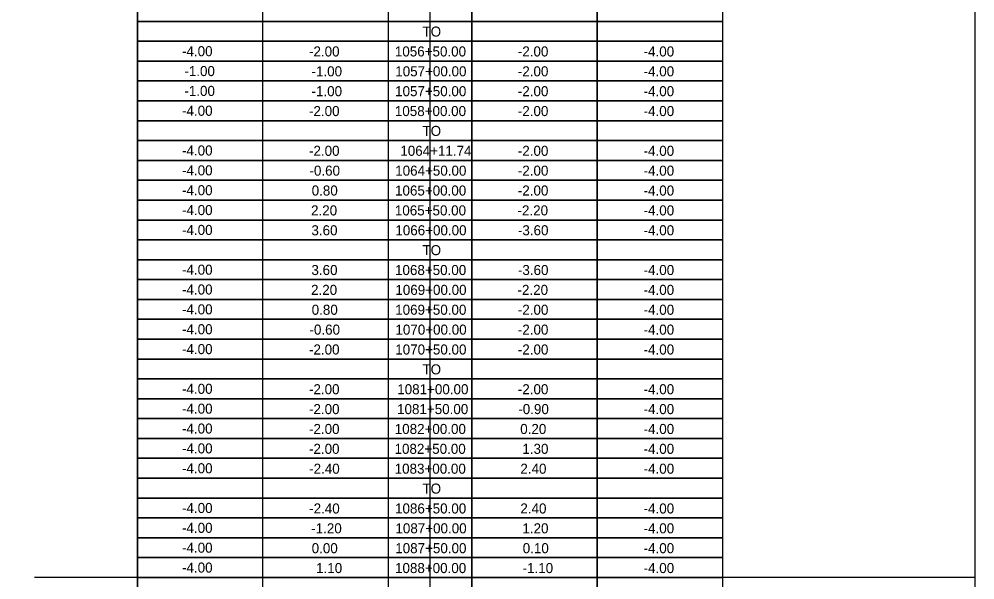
# Model space of a CAD drawing. Extents: x 1026502 to 1027102, y 781811 to 782040.
# Drawn here: x 1026944.94 to 1026990.71, y 781869.21 to 781896.04 of the extents above; entities that cross this region are included whole.
import ezdxf

# ---------------------------------------------------------------- set-up
doc = ezdxf.new("R2010")
doc.units = 0
for name, color, linetype in [('ANNOTATION', 7, 'Continuous'), ('BORDER', 7, 'Continuous'), ('DIMENSIONS', 7, 'Continuous')]:
    doc.layers.add(name, color=color, linetype=linetype)

msp = doc.modelspace()

# ---------------------------------------------------------------- linework, layer by layer
at = {"layer": 'ANNOTATION'}
for points in [[(1026917.619, 781923.493), (1026950.619, 781923.493), (1026950.619, 781846.737), (1026917.619, 781846.737)], [(1026950.619, 781923.493), (1026978.619, 781923.493), (1026978.619, 781869.32), (1026950.619, 781869.32)]]:
    msp.add_lwpolyline(points, close=True, dxfattribs=at)
at = {"layer": 'BORDER'}
for p, q in [((1026964.619, 781922.543), (1026964.619, 781816.098)), ((1026990.71, 781922.543), (1026990.71, 781816.098)), ((1026953.619, 781895.931), (1026950.619, 781895.931)), ((1026953.619, 781895.931), (1026950.619, 781895.931)), ((1026953.619, 781895.931), (1026956.619, 781895.931)), ((1026953.619, 781894.981), (1026950.619, 781894.981)), ((1026953.619, 781894.981), (1026950.619, 781894.981)), ((1026953.619, 781894.981), (1026956.619, 781894.981)), ((1026953.619, 781894.031), (1026950.619, 781894.031)), ((1026953.619, 781894.031), (1026950.619, 781894.031)), ((1026953.619, 781894.031), (1026956.619, 781894.031)), ((1026953.619, 781893.08), (1026950.619, 781893.08)), ((1026953.619, 781893.08), (1026950.619, 781893.08)), ((1026953.619, 781893.08), (1026956.619, 781893.08)), ((1026953.619, 781892.13), (1026950.619, 781892.13)), ((1026953.619, 781892.13), (1026950.619, 781892.13)), ((1026953.619, 781892.13), (1026956.619, 781892.13)), ((1026953.619, 781891.179), (1026950.619, 781891.179)), ((1026953.619, 781891.179), (1026950.619, 781891.179)), ((1026953.619, 781891.179), (1026956.619, 781891.179)), ((1026953.619, 781890.229), (1026950.619, 781890.229)), ((1026953.619, 781890.229), (1026950.619, 781890.229)), ((1026953.619, 781890.229), (1026956.619, 781890.229)), ((1026953.619, 781889.279), (1026950.619, 781889.279)), ((1026953.619, 781889.279), (1026950.619, 781889.279)), ((1026953.619, 781889.279), (1026956.619, 781889.279)), ((1026953.619, 781888.328), (1026950.619, 781888.328)), ((1026953.619, 781888.328), (1026950.619, 781888.328)), ((1026953.619, 781888.328), (1026956.619, 781888.328)), ((1026953.619, 781887.378), (1026950.619, 781887.378)), ((1026953.619, 781887.378), (1026950.619, 781887.378)), ((1026953.619, 781887.378), (1026956.619, 781887.378)), ((1026953.619, 781886.427), (1026950.619, 781886.427)), ((1026953.619, 781886.427), (1026950.619, 781886.427)), ((1026953.619, 781886.427), (1026956.619, 781886.427)), ((1026953.619, 781885.477), (1026950.619, 781885.477)), ((1026953.619, 781885.477), (1026950.619, 781885.477)), ((1026953.619, 781885.477), (1026956.619, 781885.477)), ((1026953.619, 781884.527), (1026950.619, 781884.527)), ((1026953.619, 781884.527), (1026950.619, 781884.527)), ((1026953.619, 781884.527), (1026956.619, 781884.527)), ((1026953.619, 781883.576), (1026950.619, 781883.576)), ((1026953.619, 781883.576), (1026950.619, 781883.576)), ((1026953.619, 781883.576), (1026956.619, 781883.576)), ((1026953.619, 781882.626), (1026950.619, 781882.626)), ((1026953.619, 781882.626), (1026950.619, 781882.626)), ((1026953.619, 781882.626), (1026956.619, 781882.626)), ((1026953.619, 781881.675), (1026950.619, 781881.675)), ((1026953.619, 781881.675), (1026950.619, 781881.675)), ((1026953.619, 781881.675), (1026956.619, 781881.675)), ((1026953.619, 781880.725), (1026950.619, 781880.725)), ((1026953.619, 781880.725), (1026950.619, 781880.725)), ((1026953.619, 781880.725), (1026956.619, 781880.725)), ((1026953.619, 781879.775), (1026950.619, 781879.775)), ((1026953.619, 781879.775), (1026950.619, 781879.775)), ((1026953.619, 781879.775), (1026956.619, 781879.775)), ((1026953.619, 781878.824), (1026950.619, 781878.824)), ((1026953.619, 781878.824), (1026950.619, 781878.824)), ((1026953.619, 781878.824), (1026956.619, 781878.824)), ((1026953.619, 781877.874), (1026950.619, 781877.874)), ((1026953.619, 781877.874), (1026950.619, 781877.874)), ((1026953.619, 781877.874), (1026956.619, 781877.874)), ((1026953.619, 781876.923), (1026950.619, 781876.923)), ((1026953.619, 781876.923), (1026950.619, 781876.923)), ((1026953.619, 781876.923), (1026956.619, 781876.923)), ((1026953.619, 781875.973), (1026950.619, 781875.973)), ((1026953.619, 781875.973), (1026950.619, 781875.973)), ((1026953.619, 781875.973), (1026956.619, 781875.973)), ((1026953.619, 781875.023), (1026950.619, 781875.023)), ((1026953.619, 781875.023), (1026950.619, 781875.023)), ((1026953.619, 781875.023), (1026956.619, 781875.023)), ((1026953.619, 781874.072), (1026950.619, 781874.072)), ((1026953.619, 781874.072), (1026950.619, 781874.072)), ((1026953.619, 781874.072), (1026956.619, 781874.072)), ((1026953.619, 781873.122), (1026950.619, 781873.122)), ((1026953.619, 781873.122), (1026950.619, 781873.122)), ((1026953.619, 781873.122), (1026956.619, 781873.122)), ((1026953.619, 781872.171), (1026950.619, 781872.171)), ((1026953.619, 781872.171), (1026950.619, 781872.171)), ((1026953.619, 781872.171), (1026956.619, 781872.171)), ((1026953.619, 781871.221), (1026950.619, 781871.221)), ((1026953.619, 781871.221), (1026950.619, 781871.221)), ((1026953.619, 781871.221), (1026956.619, 781871.221)), ((1026953.619, 781870.271), (1026950.619, 781870.271)), ((1026953.619, 781870.271), (1026950.619, 781870.271)), ((1026953.619, 781870.271), (1026956.619, 781870.271)), ((1026990.71, 781869.32), (1026945.675, 781869.32)), ((1026953.619, 781869.32), (1026950.619, 781869.32)), ((1026953.619, 781869.32), (1026950.619, 781869.32)), ((1026953.619, 781869.32), (1026956.619, 781869.32))]:
    msp.add_line(p, q, dxfattribs=at)
for points in [[(1026950.619, 781896.882), (1026978.619, 781896.882), (1026978.619, 781895.931), (1026950.619, 781895.931)], [(1026950.619, 781895.931), (1026978.619, 781895.931), (1026978.619, 781894.981), (1026950.619, 781894.981)], [(1026950.619, 781894.981), (1026978.619, 781894.981), (1026978.619, 781894.031), (1026950.619, 781894.031)], [(1026950.619, 781894.031), (1026978.619, 781894.031), (1026978.619, 781893.08), (1026950.619, 781893.08)], [(1026950.619, 781893.08), (1026978.619, 781893.08), (1026978.619, 781892.13), (1026950.619, 781892.13)], [(1026950.619, 781892.13), (1026978.619, 781892.13), (1026978.619, 781891.179), (1026950.619, 781891.179)], [(1026950.619, 781891.179), (1026978.619, 781891.179), (1026978.619, 781890.229), (1026950.619, 781890.229)], [(1026950.619, 781890.229), (1026978.619, 781890.229), (1026978.619, 781889.279), (1026950.619, 781889.279)], [(1026950.619, 781889.279), (1026978.619, 781889.279), (1026978.619, 781888.328), (1026950.619, 781888.328)], [(1026950.619, 781888.328), (1026978.619, 781888.328), (1026978.619, 781887.378), (1026950.619, 781887.378)], [(1026950.619, 781887.378), (1026978.619, 781887.378), (1026978.619, 781886.427), (1026950.619, 781886.427)], [(1026950.619, 781886.427), (1026978.619, 781886.427), (1026978.619, 781885.477), (1026950.619, 781885.477)], [(1026950.619, 781885.477), (1026978.619, 781885.477), (1026978.619, 781884.527), (1026950.619, 781884.527)], [(1026950.619, 781884.527), (1026978.619, 781884.527), (1026978.619, 781883.576), (1026950.619, 781883.576)], [(1026950.619, 781883.576), (1026978.619, 781883.576), (1026978.619, 781882.626), (1026950.619, 781882.626)], [(1026950.619, 781882.626), (1026978.619, 781882.626), (1026978.619, 781881.675), (1026950.619, 781881.675)], [(1026950.619, 781881.675), (1026978.619, 781881.675), (1026978.619, 781880.725), (1026950.619, 781880.725)], [(1026950.619, 781880.725), (1026978.619, 781880.725), (1026978.619, 781879.775), (1026950.619, 781879.775)], [(1026950.619, 781879.775), (1026978.619, 781879.775), (1026978.619, 781878.824), (1026950.619, 781878.824)], [(1026950.619, 781878.824), (1026978.619, 781878.824), (1026978.619, 781877.874), (1026950.619, 781877.874)], [(1026950.619, 781877.874), (1026978.619, 781877.874), (1026978.619, 781876.923), (1026950.619, 781876.923)], [(1026950.619, 781876.923), (1026978.619, 781876.923), (1026978.619, 781875.973), (1026950.619, 781875.973)], [(1026950.619, 781875.973), (1026978.619, 781875.973), (1026978.619, 781875.023), (1026950.619, 781875.023)], [(1026950.619, 781875.023), (1026978.619, 781875.023), (1026978.619, 781874.072), (1026950.619, 781874.072)], [(1026950.619, 781874.072), (1026978.619, 781874.072), (1026978.619, 781873.122), (1026950.619, 781873.122)], [(1026950.619, 781873.122), (1026978.619, 781873.122), (1026978.619, 781872.171), (1026950.619, 781872.171)], [(1026950.619, 781872.171), (1026978.619, 781872.171), (1026978.619, 781871.221), (1026950.619, 781871.221)], [(1026950.619, 781871.221), (1026978.619, 781871.221), (1026978.619, 781870.271), (1026950.619, 781870.271)], [(1026950.619, 781870.271), (1026978.619, 781870.271), (1026978.619, 781869.32), (1026950.619, 781869.32)], [(1026950.619, 781869.32), (1026978.619, 781869.32), (1026978.619, 781868.37), (1026950.619, 781868.37)]]:
    msp.add_lwpolyline(points, close=True, dxfattribs=at)
for points in [[(1026962.619, 781896.882), (1026962.619, 781895.931), (1026956.619, 781895.931), (1026956.619, 781896.882)], [(1026966.619, 781896.882), (1026966.619, 781895.931), (1026962.619, 781895.931)], [(1026972.619, 781896.882), (1026972.619, 781895.931), (1026966.619, 781895.931), (1026966.619, 781896.882)], [(1026978.619, 781896.882), (1026978.619, 781895.931), (1026972.619, 781895.931), (1026972.619, 781896.882)], [(1026962.619, 781895.931), (1026962.619, 781894.981), (1026956.619, 781894.981), (1026956.619, 781895.931)], [(1026966.619, 781895.931), (1026966.619, 781894.981), (1026962.619, 781894.981)], [(1026972.619, 781895.931), (1026972.619, 781894.981), (1026966.619, 781894.981), (1026966.619, 781895.931)], [(1026978.619, 781895.931), (1026978.619, 781894.981), (1026972.619, 781894.981), (1026972.619, 781895.931)], [(1026962.619, 781894.981), (1026962.619, 781894.031), (1026956.619, 781894.031), (1026956.619, 781894.981)], [(1026966.619, 781894.981), (1026966.619, 781894.031), (1026962.619, 781894.031)], [(1026972.619, 781894.981), (1026972.619, 781894.031), (1026966.619, 781894.031), (1026966.619, 781894.981)], [(1026978.619, 781894.981), (1026978.619, 781894.031), (1026972.619, 781894.031), (1026972.619, 781894.981)], [(1026962.619, 781894.031), (1026962.619, 781893.08), (1026956.619, 781893.08), (1026956.619, 781894.031)], [(1026966.619, 781894.031), (1026966.619, 781893.08), (1026962.619, 781893.08)], [(1026972.619, 781894.031), (1026972.619, 781893.08), (1026966.619, 781893.08), (1026966.619, 781894.031)], [(1026978.619, 781894.031), (1026978.619, 781893.08), (1026972.619, 781893.08), (1026972.619, 781894.031)], [(1026962.619, 781893.08), (1026962.619, 781892.13), (1026956.619, 781892.13), (1026956.619, 781893.08)], [(1026966.619, 781893.08), (1026966.619, 781892.13), (1026962.619, 781892.13)], [(1026972.619, 781893.08), (1026972.619, 781892.13), (1026966.619, 781892.13), (1026966.619, 781893.08)], [(1026978.619, 781893.08), (1026978.619, 781892.13), (1026972.619, 781892.13), (1026972.619, 781893.08)], [(1026962.619, 781892.13), (1026962.619, 781891.179), (1026956.619, 781891.179), (1026956.619, 781892.13)], [(1026966.619, 781892.13), (1026966.619, 781891.179), (1026962.619, 781891.179)], [(1026972.619, 781892.13), (1026972.619, 781891.179), (1026966.619, 781891.179), (1026966.619, 781892.13)], [(1026978.619, 781892.13), (1026978.619, 781891.179), (1026972.619, 781891.179), (1026972.619, 781892.13)], [(1026962.619, 781891.179), (1026962.619, 781890.229), (1026956.619, 781890.229), (1026956.619, 781891.179)], [(1026966.619, 781891.179), (1026966.619, 781890.229), (1026962.619, 781890.229)], [(1026972.619, 781891.179), (1026972.619, 781890.229), (1026966.619, 781890.229), (1026966.619, 781891.179)], [(1026978.619, 781891.179), (1026978.619, 781890.229), (1026972.619, 781890.229), (1026972.619, 781891.179)], [(1026962.619, 781890.229), (1026962.619, 781889.279), (1026956.619, 781889.279), (1026956.619, 781890.229)], [(1026966.619, 781890.229), (1026966.619, 781889.279), (1026962.619, 781889.279)], [(1026972.619, 781890.229), (1026972.619, 781889.279), (1026966.619, 781889.279), (1026966.619, 781890.229)], [(1026978.619, 781890.229), (1026978.619, 781889.279), (1026972.619, 781889.279), (1026972.619, 781890.229)], [(1026962.619, 781889.279), (1026962.619, 781888.328), (1026956.619, 781888.328), (1026956.619, 781889.279)], [(1026966.619, 781889.279), (1026966.619, 781888.328), (1026962.619, 781888.328)], [(1026972.619, 781889.279), (1026972.619, 781888.328), (1026966.619, 781888.328), (1026966.619, 781889.279)], [(1026978.619, 781889.279), (1026978.619, 781888.328), (1026972.619, 781888.328), (1026972.619, 781889.279)], [(1026962.619, 781888.328), (1026962.619, 781887.378), (1026956.619, 781887.378), (1026956.619, 781888.328)], [(1026966.619, 781888.328), (1026966.619, 781887.378), (1026962.619, 781887.378)], [(1026972.619, 781888.328), (1026972.619, 781887.378), (1026966.619, 781887.378), (1026966.619, 781888.328)], [(1026978.619, 781888.328), (1026978.619, 781887.378), (1026972.619, 781887.378), (1026972.619, 781888.328)], [(1026962.619, 781887.378), (1026962.619, 781886.427), (1026956.619, 781886.427), (1026956.619, 781887.378)], [(1026966.619, 781887.378), (1026966.619, 781886.427), (1026962.619, 781886.427)], [(1026972.619, 781887.378), (1026972.619, 781886.427), (1026966.619, 781886.427), (1026966.619, 781887.378)], [(1026978.619, 781887.378), (1026978.619, 781886.427), (1026972.619, 781886.427), (1026972.619, 781887.378)], [(1026962.619, 781886.427), (1026962.619, 781885.477), (1026956.619, 781885.477), (1026956.619, 781886.427)], [(1026966.619, 781886.427), (1026966.619, 781885.477), (1026962.619, 781885.477)], [(1026972.619, 781886.427), (1026972.619, 781885.477), (1026966.619, 781885.477), (1026966.619, 781886.427)], [(1026978.619, 781886.427), (1026978.619, 781885.477), (1026972.619, 781885.477), (1026972.619, 781886.427)], [(1026962.619, 781885.477), (1026962.619, 781884.527), (1026956.619, 781884.527), (1026956.619, 781885.477)], [(1026966.619, 781885.477), (1026966.619, 781884.527), (1026962.619, 781884.527)], [(1026972.619, 781885.477), (1026972.619, 781884.527), (1026966.619, 781884.527), (1026966.619, 781885.477)], [(1026978.619, 781885.477), (1026978.619, 781884.527), (1026972.619, 781884.527), (1026972.619, 781885.477)], [(1026962.619, 781884.527), (1026962.619, 781883.576), (1026956.619, 781883.576), (1026956.619, 781884.527)], [(1026966.619, 781884.527), (1026966.619, 781883.576), (1026962.619, 781883.576)], [(1026972.619, 781884.527), (1026972.619, 781883.576), (1026966.619, 781883.576), (1026966.619, 781884.527)], [(1026978.619, 781884.527), (1026978.619, 781883.576), (1026972.619, 781883.576), (1026972.619, 781884.527)], [(1026962.619, 781883.576), (1026962.619, 781882.626), (1026956.619, 781882.626), (1026956.619, 781883.576)], [(1026966.619, 781883.576), (1026966.619, 781882.626), (1026962.619, 781882.626)], [(1026972.619, 781883.576), (1026972.619, 781882.626), (1026966.619, 781882.626), (1026966.619, 781883.576)], [(1026978.619, 781883.576), (1026978.619, 781882.626), (1026972.619, 781882.626), (1026972.619, 781883.576)], [(1026962.619, 781882.626), (1026962.619, 781881.675), (1026956.619, 781881.675), (1026956.619, 781882.626)], [(1026966.619, 781882.626), (1026966.619, 781881.675), (1026962.619, 781881.675)], [(1026972.619, 781882.626), (1026972.619, 781881.675), (1026966.619, 781881.675), (1026966.619, 781882.626)], [(1026978.619, 781882.626), (1026978.619, 781881.675), (1026972.619, 781881.675), (1026972.619, 781882.626)], [(1026962.619, 781881.675), (1026962.619, 781880.725), (1026956.619, 781880.725), (1026956.619, 781881.675)], [(1026966.619, 781881.675), (1026966.619, 781880.725), (1026962.619, 781880.725)], [(1026972.619, 781881.675), (1026972.619, 781880.725), (1026966.619, 781880.725), (1026966.619, 781881.675)], [(1026978.619, 781881.675), (1026978.619, 781880.725), (1026972.619, 781880.725), (1026972.619, 781881.675)], [(1026962.619, 781880.725), (1026962.619, 781879.775), (1026956.619, 781879.775), (1026956.619, 781880.725)], [(1026966.619, 781880.725), (1026966.619, 781879.775), (1026962.619, 781879.775)], [(1026972.619, 781880.725), (1026972.619, 781879.775), (1026966.619, 781879.775), (1026966.619, 781880.725)], [(1026978.619, 781880.725), (1026978.619, 781879.775), (1026972.619, 781879.775), (1026972.619, 781880.725)], [(1026962.619, 781879.775), (1026962.619, 781878.824), (1026956.619, 781878.824), (1026956.619, 781879.775)], [(1026966.619, 781879.775), (1026966.619, 781878.824), (1026962.619, 781878.824)], [(1026972.619, 781879.775), (1026972.619, 781878.824), (1026966.619, 781878.824), (1026966.619, 781879.775)], [(1026978.619, 781879.775), (1026978.619, 781878.824), (1026972.619, 781878.824), (1026972.619, 781879.775)], [(1026962.619, 781878.824), (1026962.619, 781877.874), (1026956.619, 781877.874), (1026956.619, 781878.824)], [(1026966.619, 781878.824), (1026966.619, 781877.874), (1026962.619, 781877.874)], [(1026972.619, 781878.824), (1026972.619, 781877.874), (1026966.619, 781877.874), (1026966.619, 781878.824)], [(1026978.619, 781878.824), (1026978.619, 781877.874), (1026972.619, 781877.874), (1026972.619, 781878.824)], [(1026962.619, 781877.874), (1026962.619, 781876.923), (1026956.619, 781876.923), (1026956.619, 781877.874)], [(1026966.619, 781877.874), (1026966.619, 781876.923), (1026962.619, 781876.923)], [(1026972.619, 781877.874), (1026972.619, 781876.923), (1026966.619, 781876.923), (1026966.619, 781877.874)], [(1026978.619, 781877.874), (1026978.619, 781876.923), (1026972.619, 781876.923), (1026972.619, 781877.874)], [(1026962.619, 781876.923), (1026962.619, 781875.973), (1026956.619, 781875.973), (1026956.619, 781876.923)], [(1026966.619, 781876.923), (1026966.619, 781875.973), (1026962.619, 781875.973)], [(1026972.619, 781876.923), (1026972.619, 781875.973), (1026966.619, 781875.973), (1026966.619, 781876.923)], [(1026978.619, 781876.923), (1026978.619, 781875.973), (1026972.619, 781875.973), (1026972.619, 781876.923)], [(1026962.619, 781875.973), (1026962.619, 781875.023), (1026956.619, 781875.023), (1026956.619, 781875.973)], [(1026966.619, 781875.973), (1026966.619, 781875.023), (1026962.619, 781875.023)], [(1026972.619, 781875.973), (1026972.619, 781875.023), (1026966.619, 781875.023), (1026966.619, 781875.973)], [(1026978.619, 781875.973), (1026978.619, 781875.023), (1026972.619, 781875.023), (1026972.619, 781875.973)], [(1026962.619, 781875.023), (1026962.619, 781874.072), (1026956.619, 781874.072), (1026956.619, 781875.023)], [(1026966.619, 781875.023), (1026966.619, 781874.072), (1026962.619, 781874.072)], [(1026972.619, 781875.023), (1026972.619, 781874.072), (1026966.619, 781874.072), (1026966.619, 781875.023)], [(1026978.619, 781875.023), (1026978.619, 781874.072), (1026972.619, 781874.072), (1026972.619, 781875.023)], [(1026962.619, 781874.072), (1026962.619, 781873.122), (1026956.619, 781873.122), (1026956.619, 781874.072)], [(1026966.619, 781874.072), (1026966.619, 781873.122), (1026962.619, 781873.122)], [(1026972.619, 781874.072), (1026972.619, 781873.122), (1026966.619, 781873.122), (1026966.619, 781874.072)], [(1026978.619, 781874.072), (1026978.619, 781873.122), (1026972.619, 781873.122), (1026972.619, 781874.072)], [(1026962.619, 781873.122), (1026962.619, 781872.171), (1026956.619, 781872.171), (1026956.619, 781873.122)], [(1026966.619, 781873.122), (1026966.619, 781872.171), (1026962.619, 781872.171)], [(1026972.619, 781873.122), (1026972.619, 781872.171), (1026966.619, 781872.171), (1026966.619, 781873.122)], [(1026978.619, 781873.122), (1026978.619, 781872.171), (1026972.619, 781872.171), (1026972.619, 781873.122)], [(1026962.619, 781872.171), (1026962.619, 781871.221), (1026956.619, 781871.221), (1026956.619, 781872.171)], [(1026966.619, 781872.171), (1026966.619, 781871.221), (1026962.619, 781871.221)], [(1026972.619, 781872.171), (1026972.619, 781871.221), (1026966.619, 781871.221), (1026966.619, 781872.171)], [(1026978.619, 781872.171), (1026978.619, 781871.221), (1026972.619, 781871.221), (1026972.619, 781872.171)], [(1026962.619, 781871.221), (1026962.619, 781870.271), (1026956.619, 781870.271), (1026956.619, 781871.221)], [(1026966.619, 781871.221), (1026966.619, 781870.271), (1026962.619, 781870.271)], [(1026972.619, 781871.221), (1026972.619, 781870.271), (1026966.619, 781870.271), (1026966.619, 781871.221)], [(1026978.619, 781871.221), (1026978.619, 781870.271), (1026972.619, 781870.271), (1026972.619, 781871.221)], [(1026962.619, 781870.271), (1026962.619, 781869.32), (1026956.619, 781869.32), (1026956.619, 781870.271)], [(1026966.619, 781870.271), (1026966.619, 781869.32), (1026962.619, 781869.32)], [(1026972.619, 781870.271), (1026972.619, 781869.32), (1026966.619, 781869.32), (1026966.619, 781870.271)], [(1026978.619, 781870.271), (1026978.619, 781869.32), (1026972.619, 781869.32), (1026972.619, 781870.271)], [(1026962.619, 781869.32), (1026962.619, 781868.37), (1026956.619, 781868.37), (1026956.619, 781869.32)], [(1026966.619, 781869.32), (1026966.619, 781868.37), (1026962.619, 781868.37)], [(1026972.619, 781869.32), (1026972.619, 781868.37), (1026966.619, 781868.37), (1026966.619, 781869.32)], [(1026978.619, 781869.32), (1026978.619, 781868.37), (1026972.619, 781868.37), (1026972.619, 781869.32)]]:
    msp.add_lwpolyline(points, dxfattribs=at)

# ---------------------------------------------------------------- texts
at = {"layer": 'DIMENSIONS'}
for s, p in [('TO', (1026964.26, 781895.204)), ('-4.00', (1026952.745, 781894.266)), ('-2.00', (1026958.825, 781894.254)), ('1056+50.00', (1026962.937, 781894.254)), ('-2.00', (1026968.825, 781894.254)), ('-4.00', (1026974.848, 781894.254)), ('-1.00', (1026952.857, 781893.315)), ('-1.00', (1026958.946, 781893.303)), ('1057+00.00', (1026962.956, 781893.303)), ('-2.00', (1026968.825, 781893.303)), ('-4.00', (1026974.848, 781893.303)), ('-1.00', (1026952.857, 781892.365)), ('-1.00', (1026958.946, 781892.352)), ('1057+50.00', (1026962.949, 781892.352)), ('-2.00', (1026968.825, 781892.352)), ('-4.00', (1026974.848, 781892.352)), ('-4.00', (1026952.745, 781891.415)), ('-2.00', (1026958.825, 781891.401)), ('1058+00.00', (1026962.937, 781891.401)), ('-2.00', (1026968.825, 781891.401)), ('-4.00', (1026974.848, 781891.401)), ('TO', (1026964.26, 781890.45)), ('-4.00', (1026952.745, 781889.514)), ('-2.00', (1026958.825, 781889.499)), ('1064+11.74', (1026963.198, 781889.499)), ('-2.00', (1026968.825, 781889.499)), ('-4.00', (1026974.848, 781889.499)), ('-4.00', (1026952.745, 781888.563)), ('-0.60', (1026958.848, 781888.549)), ('1064+50.00', (1026962.953, 781888.549)), ('-2.00', (1026968.825, 781888.549)), ('-4.00', (1026974.848, 781888.549)), ('-4.00', (1026952.745, 781887.613)), ('0.80', (1026958.954, 781887.598)), ('1065+00.00', (1026962.945, 781887.598)), ('-2.00', (1026968.825, 781887.598)), ('-4.00', (1026974.848, 781887.598)), ('-4.00', (1026952.745, 781886.663)), ('2.20', (1026958.924, 781886.647)), ('1065+50.00', (1026962.937, 781886.647)), ('-2.20', (1026968.81, 781886.647)), ('-4.00', (1026974.848, 781886.647)), ('-4.00', (1026952.745, 781885.712)), ('3.60', (1026958.942, 781885.696)), ('1066+00.00', (1026962.96, 781885.696)), ('-3.60', (1026968.829, 781885.696)), ('-4.00', (1026974.848, 781885.696)), ('TO', (1026964.26, 781884.745)), ('-4.00', (1026952.745, 781883.811)), ('3.60', (1026958.942, 781883.794)), ('1068+50.00', (1026962.945, 781883.794)), ('-3.60', (1026968.829, 781883.794)), ('-4.00', (1026974.848, 781883.794)), ('-4.00', (1026952.745, 781882.861)), ('2.20', (1026958.924, 781882.844)), ('1069+00.00', (1026962.96, 781882.844)), ('-2.20', (1026968.81, 781882.844)), ('-4.00', (1026974.848, 781882.844)), ('-4.00', (1026952.745, 781881.911)), ('0.80', (1026958.954, 781881.893)), ('1069+50.00', (1026962.953, 781881.893)), ('-2.00', (1026968.825, 781881.893)), ('-4.00', (1026974.848, 781881.893)), ('-4.00', (1026952.745, 781880.96)), ('-0.60', (1026958.848, 781880.942)), ('1070+00.00', (1026962.964, 781880.942)), ('-2.00', (1026968.825, 781880.942)), ('-4.00', (1026974.848, 781880.942)), ('-4.00', (1026952.745, 781880.01)), ('-2.00', (1026958.825, 781879.991)), ('1070+50.00', (1026962.956, 781879.991)), ('-2.00', (1026968.825, 781879.991)), ('-4.00', (1026974.848, 781879.991)), ('TO', (1026964.26, 781879.04)), ('-4.00', (1026952.745, 781878.109)), ('-2.00', (1026958.825, 781878.089)), ('1081+00.00', (1026963.051, 781878.089)), ('-2.00', (1026968.825, 781878.089)), ('-4.00', (1026974.848, 781878.089)), ('-4.00', (1026952.745, 781877.159)), ('-2.00', (1026958.825, 781877.139)), ('1081+50.00', (1026963.043, 781877.139)), ('-0.90', (1026968.848, 781877.139)), ('-4.00', (1026974.848, 781877.139)), ('-4.00', (1026952.745, 781876.208)), ('-2.00', (1026958.825, 781876.188)), ('1082+00.00', (1026962.93, 781876.188)), ('0.20', (1026968.939, 781876.188)), ('-4.00', (1026974.848, 781876.188)), ('-4.00', (1026952.745, 781875.258)), ('-2.00', (1026958.825, 781875.237)), ('1082+50.00', (1026962.922, 781875.237)), ('1.30', (1026969.041, 781875.237)), ('-4.00', (1026974.848, 781875.237)), ('-4.00', (1026952.745, 781874.307)), ('-2.40', (1026958.833, 781874.286)), ('1083+00.00', (1026962.926, 781874.286)), ('2.40', (1026968.946, 781874.286)), ('-4.00', (1026974.848, 781874.286)), ('TO', (1026964.26, 781873.335)), ('-4.00', (1026952.745, 781872.407)), ('-2.40', (1026958.833, 781872.384)), ('1086+50.00', (1026962.945, 781872.384)), ('2.40', (1026968.946, 781872.384)), ('-4.00', (1026974.848, 781872.384)), ('-4.00', (1026952.745, 781871.456)), ('-1.20', (1026958.931, 781871.434)), ('1087+00.00', (1026962.964, 781871.434)), ('1.20', (1026969.044, 781871.434)), ('-4.00', (1026974.848, 781871.434)), ('-4.00', (1026952.745, 781870.506)), ('0.00', (1026958.954, 781870.483)), ('1087+50.00', (1026962.956, 781870.483)), ('0.10', (1026969.06, 781870.483)), ('-4.00', (1026974.848, 781870.483)), ('-4.00', (1026952.745, 781869.555)), ('1.10', (1026959.165, 781869.532)), ('1088+00.00', (1026962.945, 781869.532)), ('-1.10', (1026969.052, 781869.532)), ('-4.00', (1026974.848, 781869.532))]:
    msp.add_text(s, height=0.48, dxfattribs=at).set_placement(p)

doc.saveas('drawing.dxf')
